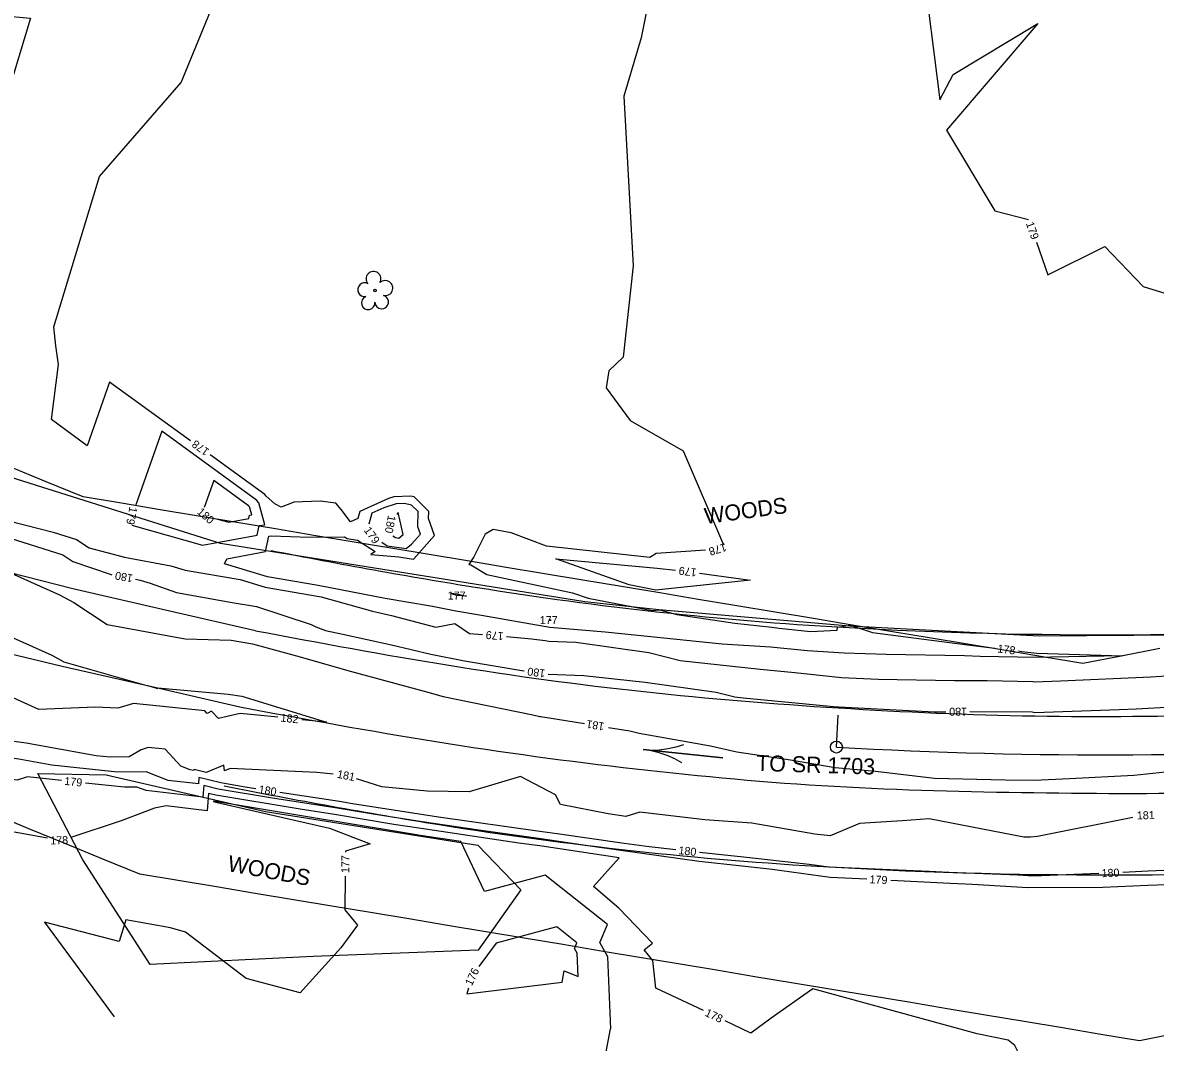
# Model space of a CAD drawing. Extents: x 2086416 to 2115205, y 575507 to 632762.
# Drawn here: x 2110919.3 to 2111202.3, y 581547.6 to 581802.4 of the extents above; entities that cross this region are included whole.
import ezdxf

# ---------------------------------------------------------------- set-up
doc = ezdxf.new("R2010")
doc.units = 0
for name, color, linetype in [('DTM Contours Major', 7, 'Continuous'), ('DTM Contours Major Text', 7, 'Continuous'), ('DTM Contours Minor', 7, 'Continuous'), ('DTM Contours Minor Text', 7, 'Continuous'), ('Exist Hydrographic FEMA Cross Section', 7, 'Continuous'), ('Exist Right of Way Line', 7, 'Continuous'), ('Exist Roads EOP', 7, 'Continuous'), ('Exist Roads EOP Text', 7, 'Continuous'), ('Exist Vegetation Tree CELL', 7, 'Continuous'), ('Exist Vegetation Woods Line', 7, 'Continuous'), ('Exist Vegetation Woods Line Text', 7, 'Continuous'), ('Prop Horizontal Alignment', 7, 'Continuous'), ('Prop Horizontal Alignment Station Label', 7, 'Continuous'), ('Prop Horizontal Alignment Tick Large', 7, 'Continuous')]:
    doc.layers.add(name, color=color, linetype=linetype)

msp = doc.modelspace()

# ---------------------------------------------------------------- linework, layer by layer
at = {"layer": 'DTM Contours Major'}
for points in [[(2110847.85, 581697.03), (2110861.11, 581691.96), (2110865.83, 581690.2), (2110868.29, 581689.26), (2110879.23, 581683.6), (2110880.71, 581683.05), (2110888.09, 581682.6), (2110898.02, 581678.3), (2110910.04, 581674.42), (2110913.9, 581674.27), (2110914.63, 581674.08), (2110929.32, 581669.43), (2110931.83, 581667.74), (2110941.39, 581664.51), (2110941.63, 581664.47)], [(2110975.78, 581681.69), (2110967.08, 581688), (2110964.7, 581681.27)], [(2110967.99, 581678.36), (2110970.82, 581677.57), (2110975.83, 581678.48), (2110976.01, 581679.35), (2110976.54, 581679.42), (2110975.97, 581681.44), (2110975.78, 581681.69)], [(2111013.31, 581673.63), (2111014.41, 581674.5), (2111013.16, 581680.03), (2111012.82, 581679.52)], [(2111011.78, 581674.22), (2111012.46, 581673.76), (2111013.31, 581673.63)], [(2110947.53, 581663.35), (2110948.69, 581663.13), (2110951.2, 581662.35), (2110957.79, 581660.03), (2110971.67, 581657.55), (2110977.7, 581656.52), (2110991.39, 581652.02), (2110992.6, 581651.48), (2110995.02, 581650.56), (2110999.28, 581649.57), (2111011.46, 581646.94), (2111021.3, 581644.58), (2111029.72, 581642.96), (2111044.53, 581640.43), (2111044.64, 581640.42)], [(2111050.59, 581639.65), (2111059.56, 581639.3), (2111074.86, 581637.63), (2111092.6, 581635.13), (2111097.3, 581633.95), (2111099.33, 581633.73), (2111122.83, 581631.48), (2111123.23, 581631.44), (2111147.14, 581630.22), (2111147.88, 581630.21), (2111150.02, 581630.22)], [(2111156.02, 581630.25), (2111171.53, 581630.22), (2111172.21, 581630.06), (2111193.33, 581630.76), (2111197.59, 581630.96), (2111217.1, 581632.04), (2111221.17, 581633.02), (2111228.47, 581633.56), (2111238.81, 581633.36), (2111247.18, 581633.58), (2111255.78, 581634.3)], [(2110977.61, 581610.99), (2110974.93, 581611.41), (2110968.79, 581612.43), (2110963.33, 581613.78), (2110963.22, 581612.21), (2110955.69, 581613.08), (2110950.2, 581615.22), (2110942.99, 581615.11), (2110926.63, 581616.85), (2110918.38, 581618.34), (2110912.82, 581619.09), (2110907.96, 581616.69), (2110897.75, 581609.63), (2110890.96, 581609.35), (2110890.33, 581609.58), (2110882.9, 581609.25)], [(2111082.5, 581595.71), (2111075.86, 581596.43), (2111069.63, 581597.3), (2111052.87, 581599.68), (2111049.12, 581600.24), (2111023.26, 581603.91), (2111019.43, 581604.48), (2111001.74, 581607.21), (2110998.51, 581607.75), (2110983.54, 581610.07)], [(2111188.19, 581589.83), (2111173.86, 581589.24), (2111170.53, 581589.23), (2111168.08, 581589.36), (2111150.72, 581590.06), (2111145.79, 581590.33), (2111120.79, 581591.36), (2111115.8, 581592.07), (2111099.43, 581593.86), (2111088.46, 581595.06)], [(2111292.84, 581594.72), (2111277, 581592.28), (2111273.44, 581591.86), (2111270.44, 581591.43), (2111253.87, 581589.01), (2111253.45, 581588.31), (2111251.32, 581587.94), (2111246.59, 581589.53), (2111241.11, 581589.81), (2111237.84, 581590.23), (2111236.11, 581589.78), (2111221.5, 581591.49), (2111210.72, 581590.77), (2111200.53, 581590.34), (2111194.18, 581590.08)]]:
    msp.add_lwpolyline(points, dxfattribs=at)
at = {"layer": 'DTM Contours Minor'}
for points in [[(2110923.11, 581896.47), (2110920.2, 581894.07), (2110908.89, 581875.53), (2110906.44, 581872.43), (2110903.92, 581871.43), (2110905.1, 581868.04), (2110902.25, 581845.78), (2110903.28, 581828.56), (2110883.48, 581824.9), (2110902.68, 581808.48), (2110906.39, 581804.92), (2110921.27, 581803.56), (2110904.76, 581749.19), (2110904.98, 581746.94)], [(2111129.93, 581874.82), (2111140.92, 581872.1), (2111139.65, 581852.84), (2111148.52, 581783.18), (2111151.82, 581789.49), (2111172.99, 581802.2), (2111150.14, 581775.57), (2111162.21, 581755.37), (2111170.68, 581753.28), (2111170.68, 581753.28)], [(2111081, 581856), (2111084.22, 581849.53), (2111082.1, 581839.99), (2111073.86, 581798.62), (2111069.52, 581784.09), (2111071.86, 581741.69), (2111069.35, 581718.81), (2111065.8, 581715.4), (2111065.15, 581711.2), (2111071.08, 581703.02), (2111084.39, 581695.44), (2111094.41, 581671.9)], [(2110961.28, 581697.94), (2110941.02, 581712.61), (2110935.39, 581696.68), (2110926.5, 581703.26), (2110928.29, 581717.02), (2110927.56, 581721.64), (2110927.09, 581726.43), (2110938.5, 581764.02), (2110958.94, 581787.46), (2110972.43, 581820.41), (2110963.81, 581829.93), (2110966.47, 581833.96)], [(2111172.65, 581747.61), (2111175.49, 581739.43), (2111189.76, 581746.49), (2111199.26, 581736.52), (2111204.94, 581734.72), (2111216.79, 581733.74), (2111237.11, 581749.36), (2111239.88, 581756.72), (2111243.14, 581765.77), (2111244.32, 581774.22), (2111268.57, 581772.28), (2111270.42, 581774.52), (2111272.15, 581778.4), (2111272.02, 581797.41), (2111269.39, 581820.52), (2111268.74, 581824.66)], [(2110905.56, 581740.96), (2110906.42, 581732.25), (2110908.99, 581715.89), (2110905.35, 581687.97), (2110900.14, 581683.3), (2110907.85, 581679.96), (2110911.1, 581678.91), (2110912.22, 581678.87), (2110926.91, 581675.14), (2110932.8, 581673.28), (2110935.94, 581671.16), (2110944.78, 581668.87), (2110956.33, 581666.68), (2110959.91, 581665.57), (2110973.62, 581663.25), (2110979.88, 581661.39), (2110993.91, 581658.93), (2111006.74, 581655.37), (2111011.49, 581654.3), (2111022.59, 581651.38), (2111027.31, 581652.26), (2111030.98, 581649.79), (2111034.24, 581649.51)], [(2110977.78, 581683.12), (2110954.05, 581700.31), (2110947.57, 581681.97)], [(2111033.98, 581654.26), (2111027.52, 581655.4), (2111021.7, 581656.52), (2111009.92, 581658.49), (2110993.12, 581661.76), (2110980.51, 581663.98), (2110969.74, 581667.17), (2110970.33, 581668.46), (2110980.03, 581670.23), (2110980.81, 581674.12), (2110981.43, 581674.2), (2110990.94, 581673.89), (2110999.77, 581673.93), (2111000.38, 581673.54), (2111003, 581673.11), (2111007.37, 581670.24), (2111006.29, 581669.55), (2111013.29, 581668.91), (2111016.9, 581668.36), (2111017.03, 581668.46), (2111022.26, 581674.27), (2111020.76, 581678.49), (2111020.77, 581680.3), (2111017.11, 581683.9), (2111016.28, 581684.11), (2111012.05, 581683.93), (2111010.72, 581683.48), (2111003.55, 581680.3), (2111003.09, 581678.48), (2111001.19, 581677.68), (2110998.91, 581680.74), (2110997.6, 581682.37), (2110993.61, 581682.82), (2110987.06, 581682.61), (2110986.89, 581682.55), (2110983.89, 581681.37), (2110982.3, 581682.15), (2110980.12, 581684.1), (2110979.79, 581684.54), (2110966.14, 581694.42)], [(2110869.92, 581683.61), (2110870.01, 581683.58), (2110872.69, 581682.19), (2110886.48, 581677.11), (2110887.21, 581677.07), (2110888.2, 581676.64), (2110900.23, 581672.75), (2110908.61, 581668.98), (2110914.95, 581666.77), (2110916.46, 581664.89), (2110928.52, 581659.48), (2110932.08, 581657.5), (2110940.41, 581652.05), (2110959.88, 581648.42), (2110971.42, 581648.11), (2110976.77, 581647.17), (2110988.63, 581643.91), (2111000.53, 581640.56), (2111020.53, 581635.11), (2111024.4, 581634.03), (2111046.82, 581629.45), (2111048.5, 581629.07), (2111048.77, 581629), (2111059.73, 581627.25)], [(2110946.57, 581676.83), (2110964.27, 581671.86), (2110977.93, 581674.36), (2110978.41, 581676.74), (2110979.85, 581676.92), (2110978.32, 581682.42), (2110977.78, 581683.12)], [(2111018.07, 581676.4), (2111018.1, 581680.27), (2111016.5, 581681.84), (2111014.71, 581682.29), (2111012.62, 581682.2), (2111009.6, 581681.2), (2111006.53, 581679.83), (2111005.84, 581677.12)], [(2111009.08, 581672.6), (2111010.38, 581671.72), (2111015.11, 581671), (2111016.46, 581672.07), (2111018.72, 581674.58), (2111018.07, 581676.4)], [(2111089.95, 581670.57), (2111077.6, 581669.79), (2111076.02, 581668.76), (2111050.2, 581671.6), (2111041.35, 581674.9), (2111036.91, 581675.75), (2111034.88, 581674.58), (2111033.37, 581671.6), (2111032.02, 581668.91), (2111030.8, 581667.04), (2111031.29, 581666.94), (2111035.33, 581664.54), (2111056.7, 581659.98), (2111060.58, 581658.59), (2111076.6, 581655.51), (2111078.42, 581655.69), (2111082.8, 581654.5), (2111097.25, 581652.4), (2111106.49, 581651.36), (2111108.31, 581651.12), (2111116.2, 581650.24), (2111122.82, 581650.6), (2111122.88, 581651.39), (2111126.12, 581651.87), (2111131.68, 581650.02), (2111155.38, 581646.96), (2111162.21, 581646.13)], [(2111070.83, 581661.91), (2111052.56, 581668.44), (2111077.82, 581666.09), (2111082.45, 581665.57)], [(2111088.41, 581664.88), (2111101.15, 581663.08), (2111077.52, 581660.62), (2111070.83, 581661.91)], [(2111027.79, 581659.26), (2111026.7, 581659.61), (2111026.31, 581659.85), (2111027.78, 581659.67), (2111027.84, 581659.66), (2111030.19, 581659.12), (2111027.79, 581659.26)], [(2111168.17, 581645.41), (2111168.97, 581645.31), (2111172.74, 581644.84), (2111194.02, 581644.23), (2111176.11, 581643.9), (2111172.57, 581643.81), (2111158.61, 581644.07), (2111154.65, 581644.18), (2111135.04, 581644.56), (2111124.61, 581644.89), (2111115.46, 581645.42), (2111106.17, 581646.37), (2111094.09, 581647.15), (2111076.28, 581648.94), (2111064.89, 581650.09), (2111051.02, 581651.31), (2111033.98, 581654.26)], [(2111050.81, 581653.14), (2111051.17, 581653.11), (2111051.34, 581653.08), (2111051.31, 581653.07), (2111051.18, 581653.08), (2111051.14, 581653.08), (2111050.81, 581653.14)], [(2110913.79, 581650.08), (2110926.59, 581644.34), (2110929.58, 581642.73), (2110948.86, 581637.16), (2110951.39, 581636.51), (2110953.03, 581636.04), (2110953.05, 581636.21), (2110970.66, 581634.65), (2110974.07, 581634.09), (2110995.24, 581627.6), (2110989.03, 581628.23)], [(2111040.21, 581649), (2111046.47, 581648.46), (2111049.91, 581648.03), (2111050.75, 581647.88), (2111057.54, 581647.61), (2111075.81, 581645.03), (2111083.62, 581643.07), (2111103.56, 581640.9), (2111112.25, 581640.07), (2111123.96, 581638.8), (2111133.06, 581638.34), (2111152.19, 581638), (2111160.29, 581638.04), (2111171.77, 581637.82), (2111172.14, 581637.73), (2111178.61, 581637.94), (2111201.19, 581638.98), (2111205.15, 581639.2), (2111206.66, 581639.57), (2111221.28, 581640.1), (2111223.41, 581640.06), (2111239.38, 581640.48)], [(2110983.07, 581628.85), (2110978, 581629.37), (2110973.65, 581629.75), (2110968.25, 581628.5), (2110966.51, 581630.36), (2110965.42, 581629.78), (2110964.79, 581630.46), (2110947.02, 581632.32), (2110943.07, 581631.1), (2110937.41, 581631.35), (2110923.38, 581630.81), (2110911.16, 581636.31)], [(2110929.04, 581613.04), (2110920.49, 581613.95), (2110917.95, 581613.11), (2110916.27, 581613.41), (2110901.27, 581603.04), (2110890.27, 581602.57), (2110889.9, 581602.71), (2110866.52, 581601.67), (2110860.13, 581604.43), (2110859.13, 581604.56), (2110830.62, 581600.5), (2110829.64, 581600.58), (2110804.08, 581605.37), (2110803.32, 581605.61), (2110774.57, 581610.97), (2110774.57, 581632.28), (2110758.83, 581634.4), (2110756.92, 581632.1)], [(2111065.66, 581626.31), (2111071.03, 581625.45), (2111073.38, 581624.88), (2111091.16, 581621.7), (2111097.77, 581620.24), (2111111.15, 581618.17), (2111122.33, 581616.26), (2111132.45, 581615.38), (2111147.13, 581613.63), (2111164.79, 581613.17), (2111172.03, 581613.12), (2111180.86, 581613.52), (2111196.96, 581614.4), (2111208.07, 581615.53), (2111221.82, 581616.87), (2111228.5, 581617.81), (2111246.33, 581620.36), (2111248.16, 581620.66), (2111254.01, 581621.76), (2111263.98, 581623.2)], [(2110996.86, 581614.66), (2110992.83, 581615.07), (2110971.13, 581616.07), (2110969.76, 581615.48), (2110969.59, 581616.9), (2110965.17, 581615), (2110962.13, 581615.76), (2110962.11, 581615.56), (2110961.19, 581615.67), (2110958.82, 581616.6), (2110954.89, 581620.84), (2110950.68, 581621.28), (2110948.91, 581620.73), (2110945.91, 581618.94), (2110941.19, 581618.86), (2110937.67, 581619.24), (2110920.18, 581622.39), (2110908.4, 581623.98)], [(2111196.72, 581603.77), (2111172.9, 581599.04), (2111171.11, 581598.89), (2111169.44, 581598.86), (2111145.84, 581603.49), (2111139.11, 581602.96), (2111128.42, 581602.29), (2111121.08, 581599.17), (2111117.24, 581599.62), (2111101.55, 581602.41), (2111089.76, 581603.22), (2111073.51, 581605.15), (2111070.03, 581604.02), (2111065.65, 581604.74), (2111053.68, 581607.05), (2111052.47, 581609.42), (2111043.72, 581614.04), (2111030.87, 581610.21), (2111020.41, 581610.41), (2111009.04, 581611.48), (2111002.71, 581613.49)], [(2111130.22, 581588.38), (2111121.05, 581588.76), (2111106.61, 581590.81), (2111099.14, 581591.63), (2111088.39, 581592.8), (2111069.38, 581595.44), (2111061.09, 581596.62), (2111048.83, 581598.45), (2111033.29, 581600.66), (2111019.16, 581602.75), (2111006.9, 581604.64), (2110997.88, 581606.14), (2110981.78, 581608.64), (2110968.18, 581610.9), (2110964.54, 581611.8), (2110964.32, 581608.85), (2110950.19, 581610.5), (2110947.86, 581611.4), (2110944.79, 581611.36), (2110935.01, 581612.4)], [(2111089.4, 581555.52), (2111077.55, 581561.12), (2111076.79, 581568.08), (2111074.63, 581570.74), (2111076.73, 581572.4), (2111068.24, 581581.12), (2111061.92, 581586.55), (2111068.35, 581593.7), (2111048.53, 581596.67), (2111043.32, 581597.41), (2111018.89, 581601.02), (2111012.06, 581602.08), (2110997.25, 581604.54), (2110988.64, 581605.87), (2110967.58, 581609.38), (2110965.75, 581609.83), (2110965.43, 581605.5), (2110955.18, 581606.69), (2110952.29, 581606.13), (2110943.89, 581602.96), (2110931.34, 581598.81)], [(2111061.52, 581539.99), (2111063.18, 581540.25), (2111064.17, 581540.37), (2111066.23, 581550.97), (2111066.29, 581550.94), (2111065.54, 581568.97), (2111063.51, 581572.55), (2111065.42, 581577.09), (2111049.84, 581589.37), (2111048.92, 581589.13), (2111034.71, 581585.33), (2111028.8, 581597.79), (2111018.62, 581599.29), (2111017.22, 581599.51), (2110996.62, 581602.93), (2110995.49, 581603.1), (2110966.97, 581607.85), (2110966.96, 581607.85), (2110966.96, 581607.82), (2110967.56, 581607.66), (2110995.97, 581601.12), (2111006.18, 581597.21), (2110999.98, 581595.42), (2110999.97, 581595.17)], [(2110925.52, 581598.64), (2110911.57, 581601.13), (2110904.79, 581596.44), (2110889.57, 581595.8), (2110889.46, 581595.84), (2110870.84, 581595.01), (2110881.93, 581586.86), (2110884.54, 581584.07), (2110886.49, 581573.95), (2110895.38, 581561.98), (2110911.97, 581539.46)], [(2110999.9, 581589.17), (2110999.8, 581580.68), (2111003.02, 581576.87), (2110998.83, 581571.21), (2110988.66, 581559.99), (2110975.14, 581563.57), (2110959.96, 581575.11), (2110956.22, 581576.23), (2110945.1, 581578.22), (2110943.43, 581572.79), (2110924.77, 581577.6), (2110942.21, 581553.94)], [(2111209.61, 581587.17), (2111200.47, 581586.79), (2111189.21, 581586.32), (2111170.47, 581586.25), (2111156.69, 581587.03), (2111151.07, 581587.26), (2111136.21, 581588.07)], [(2111058.1, 581564.04), (2111057.86, 581569.87), (2111057.2, 581571.02), (2111057.82, 581572.49), (2111052.78, 581576.47), (2111049.99, 581575.72), (2111037.65, 581572.42), (2111033.27, 581566.52)], [(2111030.73, 581561.17), (2111030.28, 581559.69), (2111054.1, 581562.6), (2111054.65, 581565.45), (2111058.1, 581564.04)], [(2111129.71, 581531.37), (2111125.41, 581541.28), (2111165.59, 581543.23), (2111162.42, 581530.29), (2111174.69, 581513.27), (2111176.23, 581530.33), (2111168.89, 581543.52), (2111167.2, 581546.79), (2111165.59, 581548.17), (2111157.85, 581549.69), (2111116.74, 581560.96), (2111106.35, 581553.66), (2111101.25, 581549.92), (2111094.82, 581552.96)]]:
    msp.add_lwpolyline(points, dxfattribs=at)
at = {"layer": 'Exist Hydrographic FEMA Cross Section'}
for points in [[(2111203.43, 581646.02), (2111193.83, 581644.15), (2111184.22, 581642.28), (2111174.61, 581643.88), (2111165.01, 581645.49), (2111155.4, 581647.09), (2111145.79, 581648.69), (2111136.18, 581650.29), (2111126.57, 581651.89), (2111116.96, 581653.49), (2111107.35, 581655.09), (2111097.75, 581656.7), (2111088.14, 581658.29), (2111078.53, 581659.9), (2111068.93, 581661.5), (2111059.32, 581663.1), (2111049.71, 581664.7), (2111040.1, 581666.3), (2111030.49, 581667.9), (2111020.89, 581669.5), (2111011.28, 581671.11), (2111001.67, 581672.71), (2110992.06, 581674.31), (2110982.45, 581675.91), (2110972.85, 581677.51), (2110963.24, 581679.11), (2110953.63, 581680.71), (2110944.03, 581682.32), (2110934.42, 581683.91), (2110925.19, 581687.7), (2110915.97, 581691.48)], [(2111207.98, 581549.87), (2111198.37, 581548), (2111188.76, 581549.6), (2111179.16, 581551.21), (2111169.55, 581552.81), (2111159.94, 581554.41), (2111150.33, 581556.01), (2111140.72, 581557.61), (2111131.11, 581559.21), (2111121.51, 581560.81), (2111111.9, 581562.41), (2111102.29, 581564.01), (2111092.68, 581565.62), (2111083.08, 581567.22), (2111073.47, 581568.82), (2111063.86, 581570.42), (2111054.26, 581572.02), (2111044.65, 581573.62), (2111035.04, 581575.22), (2111025.43, 581576.83), (2111015.82, 581578.43), (2111006.21, 581580.02), (2110996.6, 581581.63), (2110987, 581583.23), (2110977.39, 581584.83), (2110967.78, 581586.43), (2110958.18, 581588.03), (2110948.57, 581589.63), (2110939.34, 581593.42), (2110930.11, 581597.2), (2110920.89, 581600.99), (2110911.67, 581604.77)]]:
    msp.add_lwpolyline(points, dxfattribs=at)
at = {"layer": 'Exist Right of Way Line'}
for centre, radius, start, end in [((2111262.84, 583087.65), 1444.79, 258.76631, 260.84314), ((2111174.98, 582542.55), 892.65, 260.84314, 266.74835), ((2111190.81, 582821.14), 1171.69, 266.74835, 273.81807), ((2111262.84, 583087.65), 1504.79, 258.76631, 260.84314), ((2111174.98, 582542.55), 952.65, 260.84314, 266.74835), ((2111190.81, 582821.14), 1231.69, 266.74835, 273.81807)]:
    msp.add_arc(centre, radius, start, end, dxfattribs=at)
at = {"layer": 'Exist Roads EOP'}
for points in [[(2110977.48, 581650.48), (2110956.38, 581655.31), (2110931.86, 581660.94), (2110907.94, 581667.06), (2110884.07, 581673.67), (2110859.62, 581680.71)], [(2110910.76, 581646.06), (2110929.15, 581641.61), (2110951.61, 581636.54), (2110973.54, 581631.44)]]:
    msp.add_lwpolyline(points, dxfattribs=at)
for points in [[(2110977.48, 581650.48), (2111025.79, 581641.84), (2111074.55, 581635.25), (2111123.2, 581631.18), (2111172.22, 581629.18), (2111221.29, 581629.52), (2111270.17, 581631.7), (2111319.13, 581635.84), (2111368.33, 581641.12), (2111417.78, 581647.42)], [(2110973.54, 581631.44), (2111022.55, 581622.76), (2111072.45, 581615.95), (2111122.07, 581611.59), (2111171.98, 581610.01), (2111221.99, 581610.11), (2111271.48, 581612.54), (2111320.96, 581616.67), (2111370.32, 581622.18), (2111419.52, 581628.55)]]:
    msp.add_spline(points, degree=3, dxfattribs=at)
at = {"layer": 'Exist Roads EOP Text'}
msp.add_line((2111084.29, 581619.75), (2111084.29, 581619.75), dxfattribs=at)
msp.add_lwpolyline([(2111084.06, 581617.48), (2111082.26, 581618.45), (2111080.36, 581619.29), (2111078.38, 581619.97), (2111076.37, 581620.49), (2111074.34, 581620.77), (2111094.24, 581618.73), (2111074.34, 581620.77), (2111076.39, 581620.64), (2111078.46, 581620.74), (2111080.54, 581621.01), (2111082.57, 581621.44), (2111084.52, 581622.03)], dxfattribs=at)
at = {"layer": 'Exist Vegetation Tree CELL'}
msp.add_line((2111007.35, 581735.51), (2111007.35, 581735.51), dxfattribs=at)
msp.add_circle((2111007.35, 581735.51), 0.326, dxfattribs=at)
for centre, radius, start, end in [((2111006.97, 581738.39), 1.86, 330.1651, 219.7134), ((2111004.75, 581735.67), 1.73, 62.6636, 279.3457), ((2111009.9, 581736.1), 1.9, 257.1011, 134.1999), ((2111005.65, 581732.39), 1.69, 111.5671, 6.231), ((2111009.02, 581732.61), 1.7, 181.2822, 74.56)]:
    msp.add_arc(centre, radius, start, end, dxfattribs=at)
at = {"layer": 'Exist Vegetation Woods Line'}
for points in [[(2111059.79, 581657.65), (2110968.73, 581672.25), (2110864.06, 581705.25), (2110784.73, 581740.8), (2110702.3, 581784.67), (2110632.54, 581823.34), (2110568.48, 581865.95), (2110498.27, 581913.79), (2110441.66, 581966.78), (2110387.94, 582016.39), (2110334.43, 582063.69), (2110284.48, 582120.87)], [(2111452.1, 581736.22), (2111479.27, 581697.5), (2111499.68, 581677.78), (2111492.04, 581671.34), (2111416.64, 581665.13), (2111367.28, 581660.93), (2111318.17, 581654.2), (2111268.32, 581650.61), (2111220.66, 581649.45), (2111173.29, 581649.12), (2111125.98, 581651.57), (2111078.27, 581655.72), (2111059.79, 581657.65)], [(2111033.08, 581596.9), (2111043.81, 581585.75), (2111033.1, 581570.65), (2110991.9, 581569.03), (2110951.17, 581567.08), (2110934.36, 581593.21), (2110923.1, 581614.81), (2110940.19, 581614.48)], [(2110940.19, 581614.48), (2110979.98, 581605.26), (2111033.08, 581596.9)]]:
    msp.add_lwpolyline(points, dxfattribs=at)
at = {"layer": 'Prop Horizontal Alignment'}
msp.add_arc((2111190.81, 582821.14), 1201.69, 266.74835, 273.81807, dxfattribs=at)
at = {"layer": 'Prop Horizontal Alignment Station Label'}
msp.add_circle((2111122.64, 581621.39), 1.5, dxfattribs=at)
at = {"layer": 'Prop Horizontal Alignment Tick Large'}
msp.add_line((2111122.64, 581621.39), (2111123.1, 581629.37), dxfattribs=at)

# ---------------------------------------------------------------- texts
at = {"layer": 'DTM Contours Major Text'}
for rotation, p in [(318.4729, (2110962.73, 581679.93)), (258.9078, (2111010.63, 581679.44)), (169.2205, (2110947, 581664.46)), (172.687, (2111050, 581640.74)), (180.2575, (2111155.29, 581631.25)), (351.1764, (2110978.17, 581609.89)), (353.7627, (2111083.11, 581594.64)), (2.3706, (2111188.95, 581588.86))]:
    msp.add_text('180', height=2, rotation=rotation, dxfattribs=at).set_placement(p)
at = {"layer": 'DTM Contours Minor Text'}
for s, rotation, p in [('179', 289.177, (2111169.97, 581752.27)), ('178', 144.084, (2110966.14, 581695.65)), ('179', 258.9249, (2110946.03, 581681.57)), ('179', 305.664, (2111004.47, 581675.57)), ('178', 196.5393, (2111094.84, 581672.37)), ('179', 173.3517, (2111087.81, 581665.97)), ('179', 175.0859, (2111039.58, 581650.05)), ('178', 353.109, (2111162.81, 581645.05)), ('182', 354.1396, (2110983.68, 581627.78)), ('181', 170.9505, (2111064.77, 581627.46)), ('179', 353.9173, (2110929.65, 581611.97)), ('181', 348.7424, (2110997.75, 581613.75)), ('181', 1.4931, (2111197.75, 581603.3)), ('178', 1.661, (2110926.23, 581597.04)), ('177', 89.2978, (2111000.91, 581589.88)), ('179', 357.0364, (2111130.89, 581587.36)), ('176', 64.5646, (2111031.54, 581561.56)), ('178', 334.6984, (2111089.62, 581554.31))]:
    msp.add_text(s, height=2, rotation=rotation, dxfattribs=at).set_placement(p)
for p in [(2111025.52, 581658.26), (2111048.53, 581652.14)]:
    msp.add_text('177', height=2, dxfattribs=at).set_placement(p)
at = {"layer": 'Exist Roads EOP Text'}
msp.add_text('TO SR 1703', height=4, rotation=358.234, dxfattribs=at).set_placement((2111102.54, 581615.43))
at = {"layer": 'Exist Vegetation Woods Line Text'}
for rotation, p in [(7.771, (2111089.94, 581677.1)), (349.5682, (2110970.32, 581590.44))]:
    msp.add_text('WOODS', height=4, rotation=rotation, dxfattribs=at).set_placement(p)

doc.saveas('drawing.dxf')
